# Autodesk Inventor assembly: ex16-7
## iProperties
Shininess: 64.0
Length Units: 11269
Angle Units: 11279
Time Units: 11290
Mass Units: 11283
Length Display Precision: 3
Angle Display Precision: 2
Compacted: True
Created: 2002-11
Part Number: ex16-7
Document SubType Name: Assembly
Designer: E. MOSS
Density: 0.0
Volumn: 0.0
Area: 0.0
PropertySet Name: Model Information
Control State: 0
Master: False
Checked Out: False
Author: E. MOSS
